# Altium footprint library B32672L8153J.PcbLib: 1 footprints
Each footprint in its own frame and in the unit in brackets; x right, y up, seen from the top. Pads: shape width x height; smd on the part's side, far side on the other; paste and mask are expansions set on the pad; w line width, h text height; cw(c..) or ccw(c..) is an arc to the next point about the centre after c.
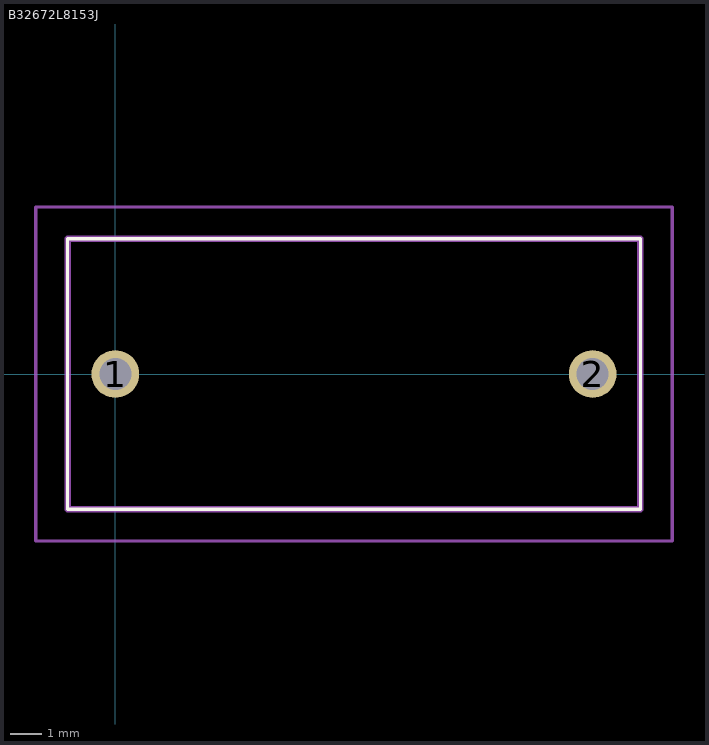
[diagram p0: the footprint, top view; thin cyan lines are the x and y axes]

## B32672L8153J [mm]
pads (2):
  round 1.5 hole 1: 1(0,0) 2(15,0)
Top Overlay:
  lines w0.1: -1.5,-4.25 16.5,-4.25 16.5,4.25 -1.5,4.25 -1.5,-4.25
Mechanical 15:
  lines w0.2: -1.5,-4.25 16.5,-4.25 16.5,4.25 -1.5,4.25 -1.5,-4.25
Mechanical 20:
  lines w0.1: -2.5,-5.25 17.5,-5.25 17.5,5.25 -2.5,5.25 -2.5,-5.25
